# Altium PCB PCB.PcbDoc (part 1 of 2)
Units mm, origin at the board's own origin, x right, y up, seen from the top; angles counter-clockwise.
Board outline 40.89 x 35.18 mm, 4 copper layers (Top Layer, Signal Layer 1, Signal Layer 2, Bottom Layer), stack 1.554 mm thick; 53 components, 28 nets, 142 pads, 33 vias.
Unrouted connection lines stored in the file: 4.
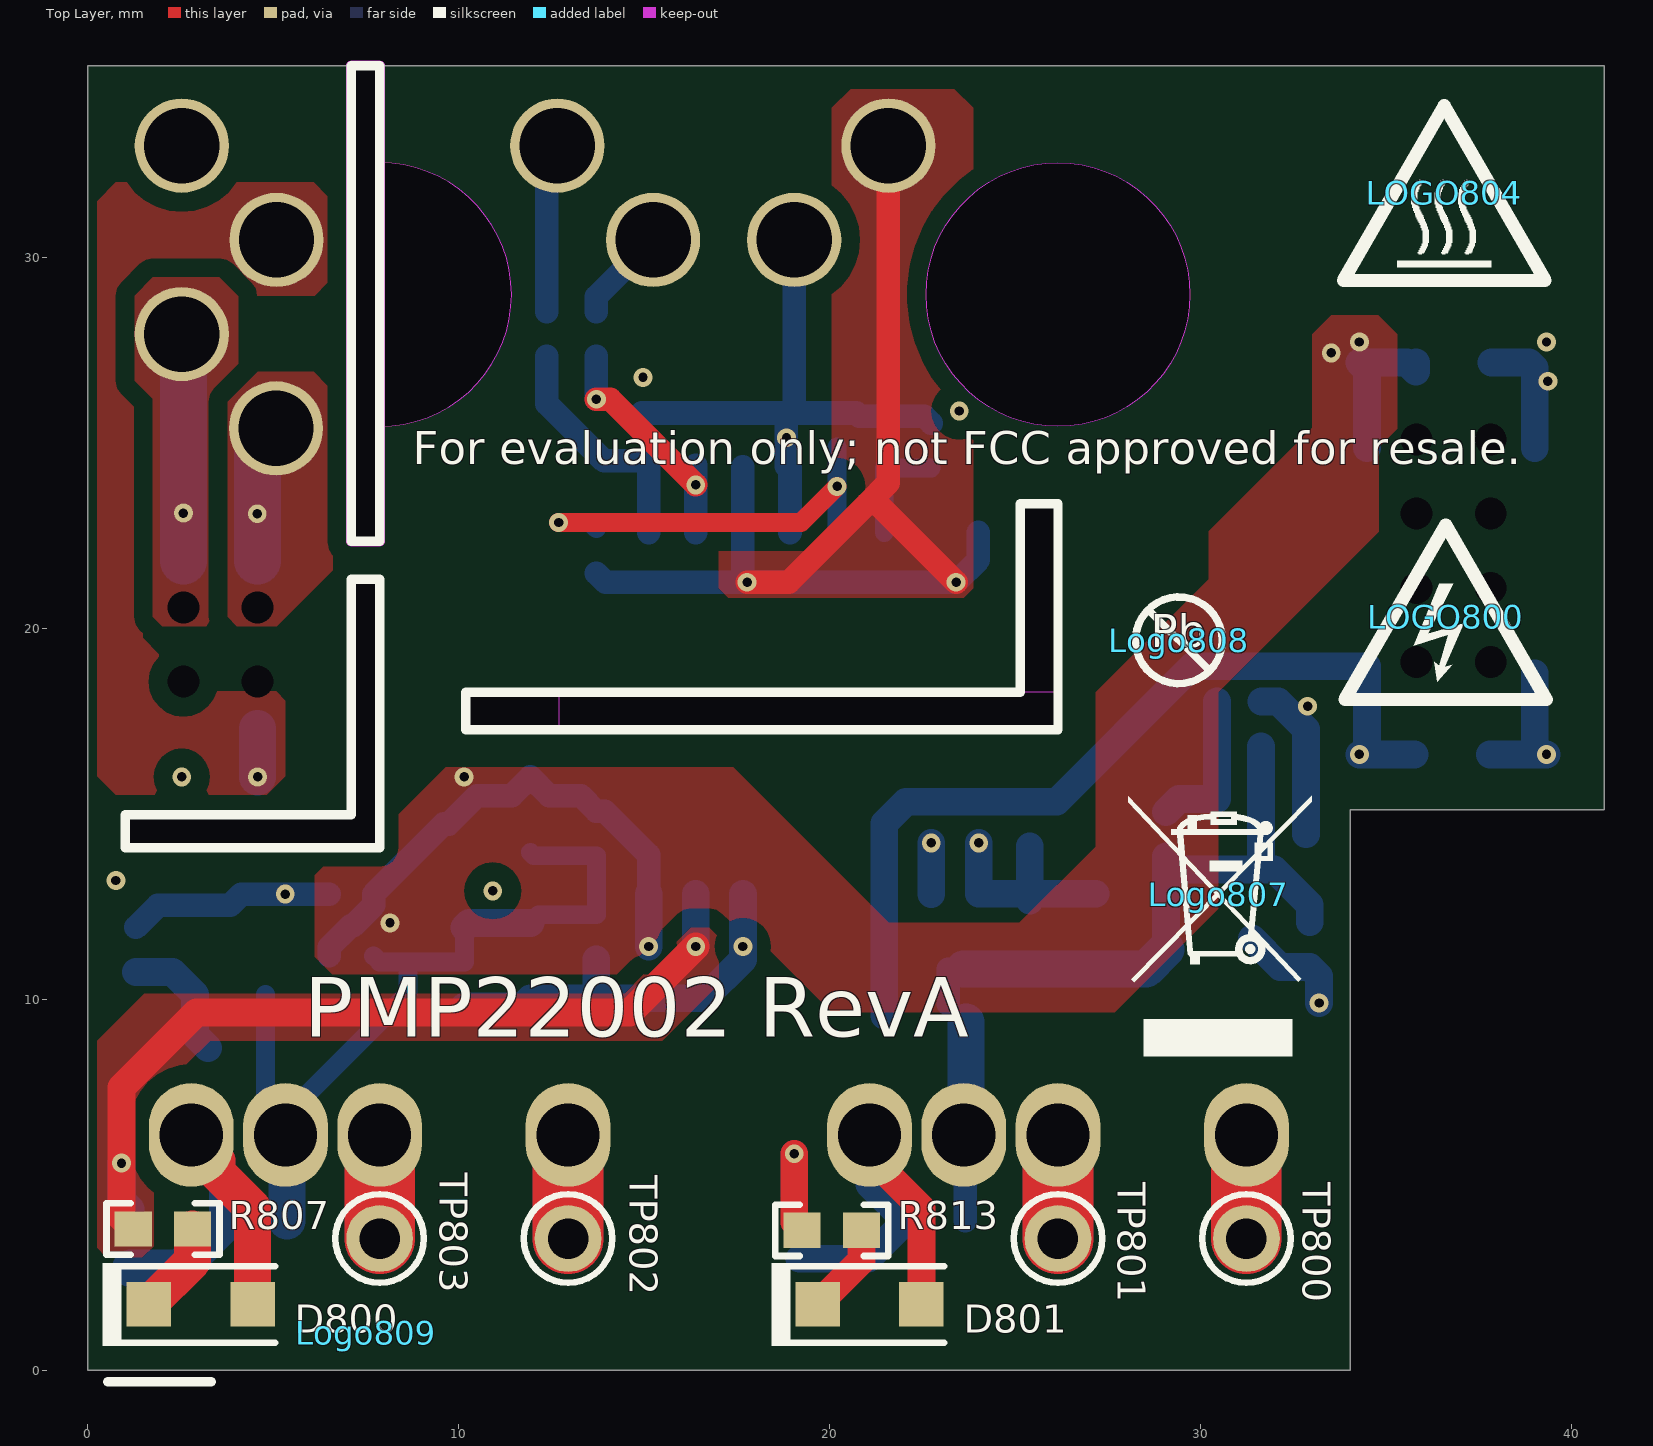
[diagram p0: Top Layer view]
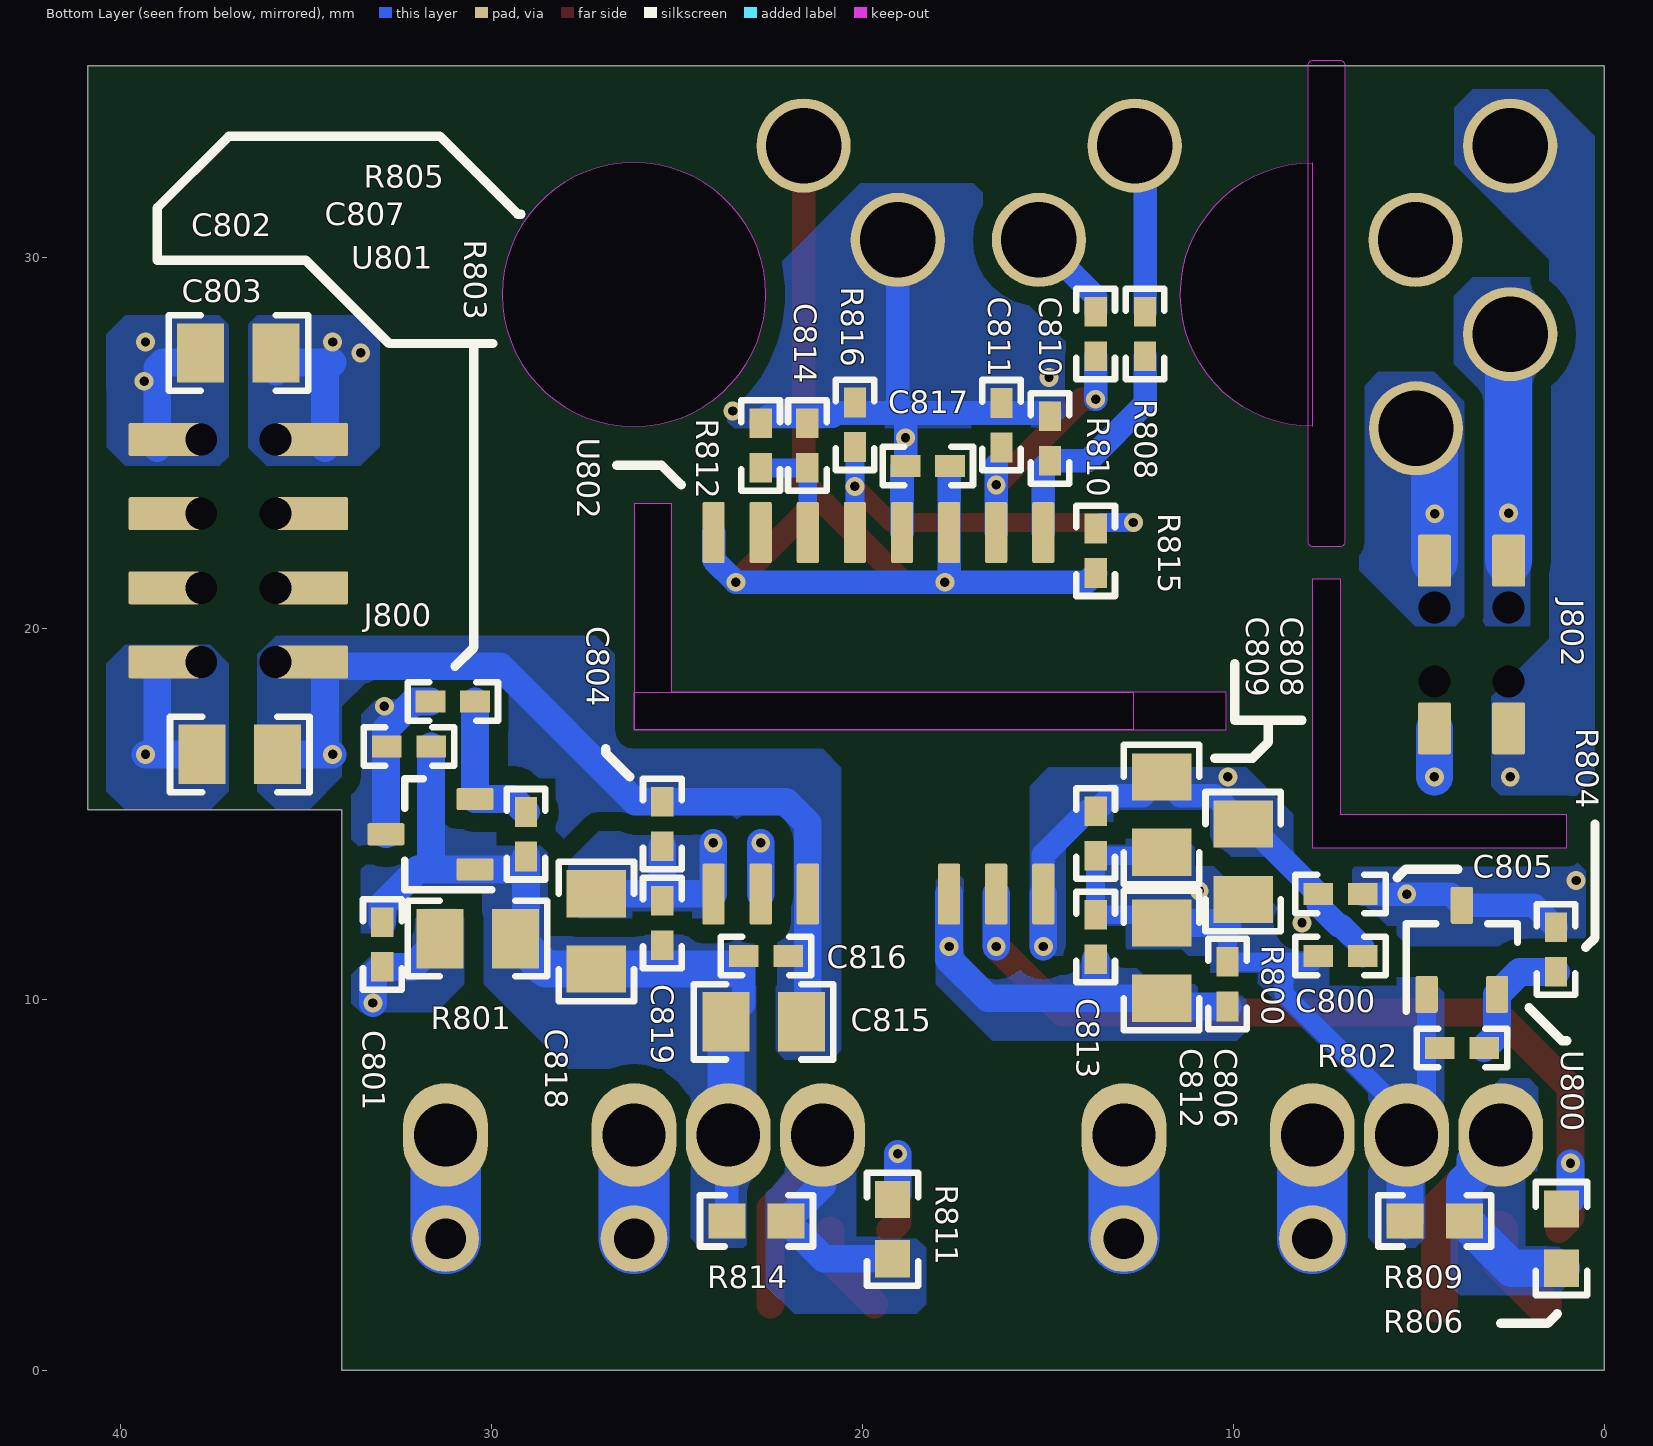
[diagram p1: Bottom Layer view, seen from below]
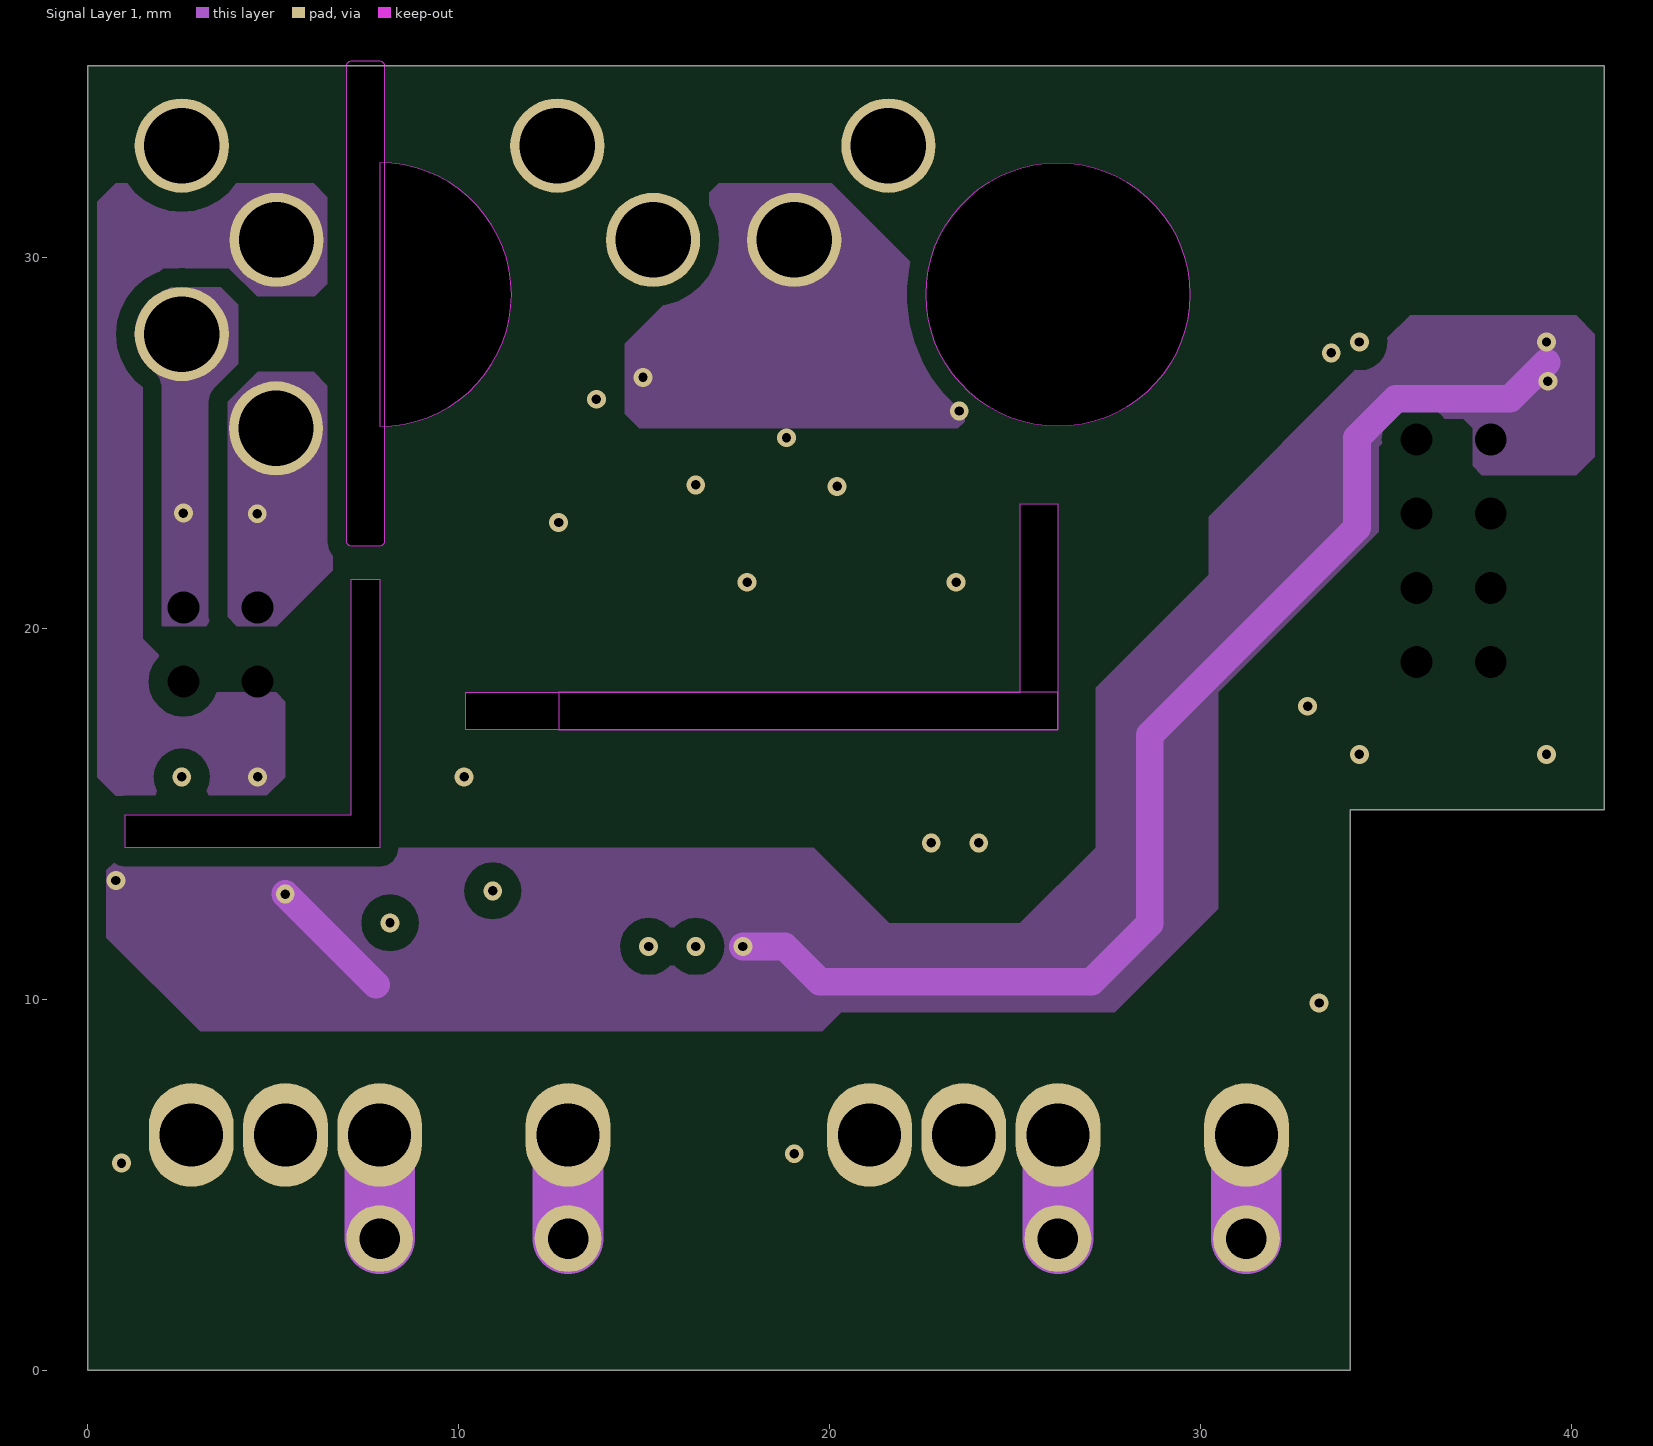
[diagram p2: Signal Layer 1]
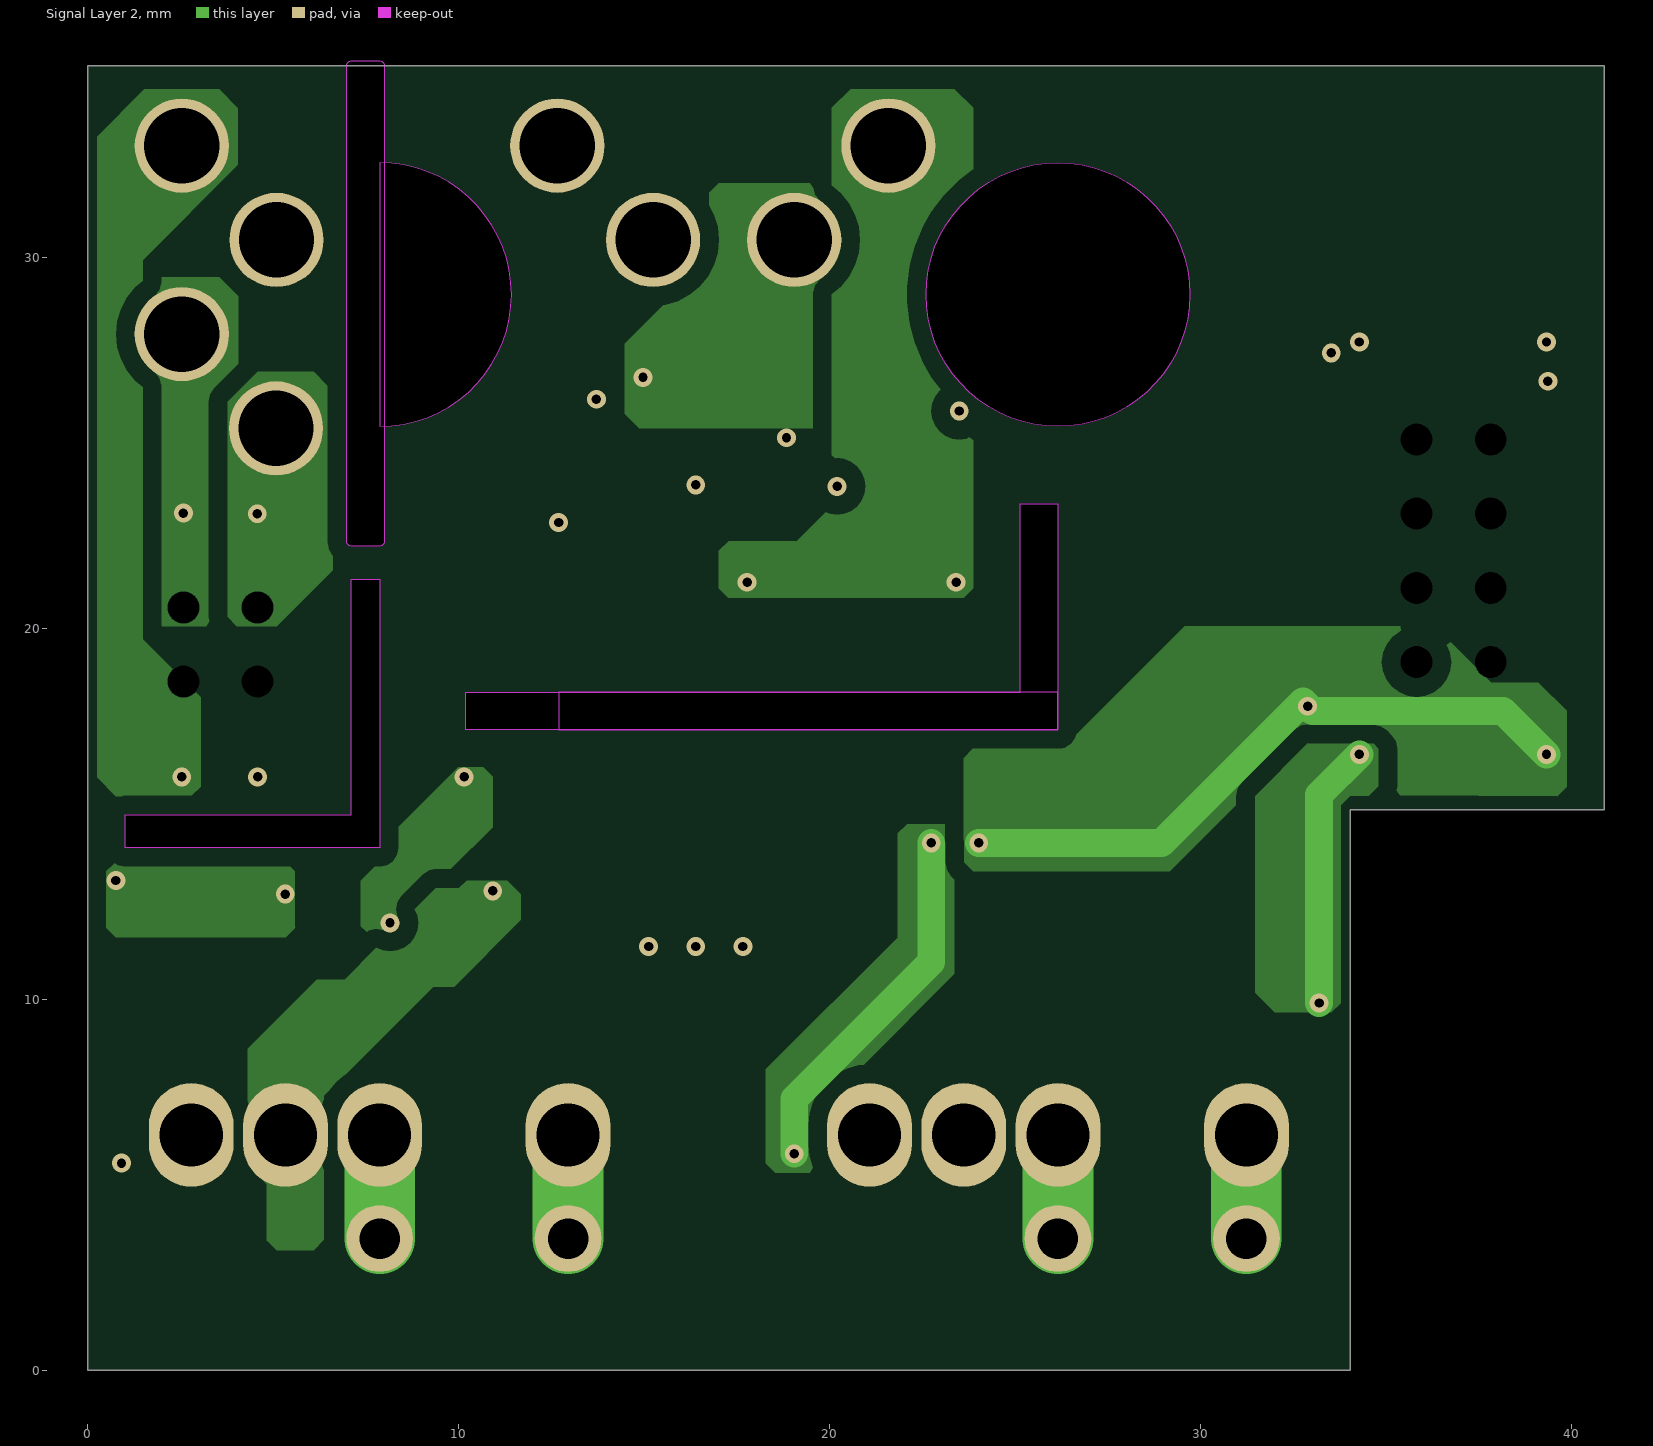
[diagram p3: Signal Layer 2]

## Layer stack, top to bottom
Top Solder: solder mask 0.0102, Solder Resist, Dk 3.5
Top Layer: signal copper 0.0356
Dielectric 3: dielectric 0.1981, Dk 4.2
Signal Layer 1: signal copper 0.0356
Dielectric 2: core 1.016, FR-4, Dk 4.2
Signal Layer 2: signal copper 0.0356
Dielectric 4: dielectric 0.1981, Dk 4.2
Bottom Layer: signal copper 0.0356
Bottom Solder: solder mask 0.0102, Solder Resist, Dk 3.5

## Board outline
0,0 0,35.179 40.894,35.179 40.894,15.113 34.036,15.113 34.036,0
cut-out: 10.191,17.272 10.191,18.288 25.146,18.288 25.146,23.368 26.162,23.368 26.162,17.272
cut-out: 12.7,17.272 26.162,17.272 26.162,18.288 12.7,18.288
cut-out: 1.016,14.097 1.016,14.986 7.112,14.986 7.112,21.336 7.874,21.336 7.874,14.097
cut-out: 7.112,22.225 cw(c7.112,22.352) 6.985,22.352 6.985,35.179 cw(c7.112,35.179) 7.112,35.306 7.874,35.306 cw(c7.874,35.179) 8.001,35.179 8.001,22.352 cw(c7.874,22.352) 7.874,22.225
cut-out: 7.874,25.451 ccw(c7.874,29.007) 7.874,32.563
cut-out: 26.162,25.451 cw(c26.162,29.007) 22.606,29.007 cw(c26.162,29.007) 26.162,32.563 cw(c26.162,29.007) 29.718,29.007 cw(c26.162,29.007)

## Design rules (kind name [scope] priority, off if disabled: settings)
AcuteAngle [All] p1: minimum=4.50000000000000E+0001 checktracksonly=FALSE
AssemblyTestPointUsage [All] p1: valid=2
Clearance Clearance_2 [InNetClass('HV') vs Not InNetClass('HV')] p1: gap=1.27 ignorepadtopadclearanceinfootprint=FALSE except(0: Arc-Hole Track-Hole SMDPad-Hole THPad-Hole Via-Hole Fill-Hole Poly-Hole Region-Hole Text-Hole)
Clearance Clearance_1 [InNetClass('MV') vs Not InNetClass('MV')] p2: gap=0.508 ignorepadtopadclearanceinfootprint=FALSE
Clearance Clearance_Keepouts [((IsTrack Or IsArc) And Not InPoly) And IsFree and IsKeepOut vs ((IsTrack Or IsArc) And Not InPoly) And IsFree and IsKeepOut] p3: gap=0 ignorepadtopadclearanceinfootprint=FALSE
Clearance Clearance_BoardEdge_MountingHoles [OnCopper and InComponentClass('Mounting Holes') vs IsKeepOut] p4: gap=1.016 ignorepadtopadclearanceinfootprint=FALSE except(0: Arc-Hole Track-Hole SMDPad-Hole THPad-Hole Via-Hole Fill-Hole Poly-Hole Region-Hole Text-Hole)
Clearance Clearance_BoardEdge_Poly [OnCopper and InPoly vs IsKeepOut] p5: gap=0.635 ignorepadtopadclearanceinfootprint=FALSE except(0: Arc-Hole Track-Hole SMDPad-Hole THPad-Hole Via-Hole Fill-Hole Poly-Hole Region-Hole Text-Hole)
Clearance Clearance_BoardEdge [OnCopper and Not InComponentClass('Logo') and not InComponentClass('FiducialMark') and not InRegion(1000,500,4000,800) and Not IsKeepout vs IsKeepOut] p6: gap=1.905 ignorepadtopadclearanceinfootprint=FALSE except(0: Arc-Hole Track-Hole SMDPad-Hole THPad-Hole Via-Hole Fill-Hole Poly-Hole Region-Hole Text-Hole)
Clearance Clearance_Poly [InPolygon] p7: gap=0.508 ignorepadtopadclearanceinfootprint=FALSE except(0: Arc-Hole Track-Hole SMDPad-Hole THPad-Hole Via-Hole Fill-Hole Poly-Hole Region-Hole Text-Hole)
Clearance [All] p8: gap=0.2 ignorepadtopadclearanceinfootprint=FALSE except(0: Arc-Hole Track-Hole SMDPad-Hole THPad-Hole Via-Hole Fill-Hole Poly-Hole Region-Hole Text-Hole)
ComponentClearance ComponentClearance_MountingHoles_FiducialMarks [InComponentClass('Mounting Holes') vs InComponentClass('FiducialMark')] p1: gap=0.508 collisioncheckmode=3 verticalgap=0.254 showdistances=FALSE
ComponentClearance ComponentClearance_Shunt [InComponentClass('Header') vs InComponentClass('Shunt')] p2: gap=0 collisioncheckmode=3 verticalgap=0 showdistances=FALSE
ComponentClearance ComponentClearance_Logo [InComponentClass('Logo')] p3: gap=0.127 collisioncheckmode=3 verticalgap=0.254 showdistances=FALSE
ComponentClearance ComponentClearance_ScrewToNut [(HasFootprint('NY PMS 440 0025 PH')) vs (HasFootprint('Keystone_1902C'))] p4: gap=0.508 collisioncheckmode=3 verticalgap=2540 showdistances=FALSE
ComponentClearance ComponentClearance_MountingHoles [InComponentClass('Mounting Holes')] p5: gap=0.508 collisioncheckmode=3 verticalgap=0.254 showdistances=FALSE
ComponentClearance ComponentClearance_SmallPassives [HasFootprint('0201*') or HasFootprint('0402*') or HasFootprint('0508') or HasFootprint('0603*') or HasFootprint('0612') or HasFootprint('0805*') or HasFootprint('0815*') or HasFootprint('0830*') or HasFootprint('1206*') or HasFootprint('1210*') or HasFootprint('1808*') or HasFootprint('1812*') or HasFootprint('1825*') or HasFootprint('2010*') or HasFootprint('2220*') or HasFootprint('2225*') or HasFootprint('2512*') or HasFootprint('2728*') or HasFootprint('3518*') vs HasFootprint('0201*') or HasFootprint('0402*') or HasFootprint('0508') or HasFootprint('0603*') or HasFootprint('0612') or HasFootprint('0805*') or HasFootprint('0815*') or HasFootprint('0830*') or HasFootprint('1206*') or HasFootprint('1210*') or HasFootprint('1808*') or HasFootprint('1812*') or HasFootprint('1825*') or HasFootprint('2010*') or HasFootprint('2220*') or HasFootprint('2225*') or HasFootprint('2512*') or HasFootprint('2728*') or HasFootprint('3518*')] p6: gap=0.508 collisioncheckmode=3 verticalgap=0.508 showdistances=FALSE
ComponentClearance ComponentClearance_THtoSMT [IsThruComponent vs IsSMTComponent] p7: gap=0.254 collisioncheckmode=3 verticalgap=0.254 showdistances=FALSE
ComponentClearance ComponentClearance_THtoTH [IsThruComponent vs IsThruComponent] p8: gap=0.254 collisioncheckmode=3 verticalgap=0.254 showdistances=FALSE
ComponentClearance [All] p9: gap=0.254 collisioncheckmode=3 verticalgap=0.254 showdistances=FALSE
DiffPairsRouting [All] p1: maxlimit=2.54 minlimit=0.254 mostfreqgap=0.254 toplayer_minwidth=0.381 toplayer_maxwidth=0.381 toplayer_prefwidth=0.381 midlayer1_minwidth=0.381 midlayer1_maxwidth=0.381 midlayer1_prefwidth=0.381 midlayer2_minwidth=0.381 midlayer2_maxwidth=0.381 midlayer2_prefwidth=0.381 bottomlayer_minwidth=0.381 bottomlayer_maxwidth=0.381 bottomlayer_prefwidth=0.381 maxuncoupledlength=25.4
FabricationTestPointUsage TestPointUsage [All] p1: valid=2 allowmultiple=FALSE
FabricationTestpoint Testpoint [All] p1: side=3 testpointundercomponent=TRUE minsize=1.016 maxsize=2.54 preferedsize=1.524 minholesize=0 maxholesize=1.016 preferedholesize=0.813 testpointgrid=0.025 allowsidetop=TRUE allowsidebottom=TRUE usegrid=TRUE gridtolerance=0
FanoutControl Fanout_LCC [IsLCC] p1: bgadir=Out bgaviamode=Centered fanoutstyle=Auto fanoutdirection=Alternating viagrid=0.025 // Fanout_LCC (Default Rule)
FanoutControl Fanout_BGA [IsBGA] p2: bgadir=Out bgaviamode=Centered fanoutstyle=Auto fanoutdirection=Alternating viagrid=0.025 // Fanout_BGA (Default Rule)
FanoutControl Fanout_Default [All] p4: bgadir=Out bgaviamode=Centered fanoutstyle=Auto fanoutdirection=Alternating viagrid=0.025 // Fanout_Default (Default Rule)
FanoutControl Fanout_Small [(CompPinCount < 5)] p5: bgadir=Out bgaviamode=Centered fanoutstyle=Auto fanoutdirection=OutThenIn viagrid=0.025 // Fanout_Small (Default Rule)
Height [All] p1: minheight=0 maxheight=76.2 prefheight=12.7
HoleSize [All] p1: absolutevalues=TRUE maxlimit=6.375 minlimit=0.178 maxpercent=80.000 minpercent=20.000
MinimumAnnularRing MinimumAnnularRing_ThermalPadVias [IsVia and InAnyComponent] p1: minimumring=0.15
MinimumAnnularRing [All] p2: minimumring=0.124
MinimumSolderMaskSliver MinimumSolderMaskSliver_Logo [InComponentClass('Logo') vs InComponentClass('Logo')] p1: minsoldermaskwidth=0.018
MinimumSolderMaskSliver [All] p2: minsoldermaskwidth=0.051
PlaneConnect [All] p1: planeconnectstyle=Direct reliefexpansion=0.254 reliefentries=4 reliefconductorwidth=0.254 reliefairgap=0.254
PolygonConnect PolygonConnect_23 [All vs IsNamedPolygon('PGND') Or  IsNamedPolygon('5Vp') Or  IsNamedPolygon('PGND') Or  IsNamedPolygon('PGND') Or  IsNamedPolygon('PGND') Or  IsNamedPolygon('5Vp') Or  IsNamedPolygon('5Vp') Or  IsNamedPolygon('5Vp') Or  IsNamedPolygon('+VA') Or  IsNamedPolygon('-VA') Or  IsNamedPolygon('Vg1') Or  IsNamedPolygon('R806_1') Or  IsNamedPolygon('PGND') Or  IsNamedPolygon('5Vp') Or  IsNamedPolygon('Vg1') Or  IsNamedPolygon('Vg2') Or  IsNamedPolygon('Vg2') Or  IsNamedPolygon('+VB') Or  IsNamedPolygon('R811_1') Or  IsNamedPolygon('+VA') Or  IsNamedPolygon('-VA') Or  IsNamedPolygon('-VB') Or  IsNamedPolygon('-VB') Or  IsNamedPolygon('-VB') Or  IsNamedPolygon('+VB') Or  IsNamedPolygon('+VB') Or  IsNamedPolygon('COMB') Or  IsNamedPolygon('-VB') Or  IsNamedPolygon('VGB') Or  IsNamedPolygon('VGA') Or  IsNamedPolygon('-VA') Or  IsNamedPolygon('+VA') Or  IsNamedPolygon('Coma') Or  IsNamedPolygon('-VA') Or  IsNamedPolygon('+VA') Or  IsNamedPolygon('Coma') Or  IsNamedPolygon('-VA') Or  IsNamedPolygon('PGND') Or  IsNamedPolygon('PGND') Or  IsNamedPolygon('5Vp')] p1: connectstyle=Direct reliefconductorwidth=0.254 reliefentries=4 polygonreliefangle="90 Angle" airgapwidth=0.254
PolygonConnect PolygonConnect_22 [All vs IsNamedPolygon('+VB') Or  IsNamedPolygon('PGND') Or  IsNamedPolygon('VGB') Or  IsNamedPolygon('VGA') Or  IsNamedPolygon('+VA') Or  IsNamedPolygon('-VA') Or  IsNamedPolygon('5Vp') Or  IsNamedPolygon('5Vp') Or  IsNamedPolygon('+VA') Or  IsNamedPolygon('Vg2') Or  IsNamedPolygon('Coma') Or  IsNamedPolygon('-VA') Or  IsNamedPolygon('Vg2') Or  IsNamedPolygon('-VB') Or  IsNamedPolygon('PGND') Or  IsNamedPolygon('Vg2') Or  IsNamedPolygon('PGND') Or  IsNamedPolygon('-VA') Or  IsNamedPolygon('5Vp') Or  IsNamedPolygon('+VA') Or  IsNamedPolygon('5Vp') Or  IsNamedPolygon('PGND') Or  IsNamedPolygon('PGND') Or  IsNamedPolygon('PGND') Or  IsNamedPolygon('Coma') Or  IsNamedPolygon('5Vp') Or  IsNamedPolygon('PGND') Or  IsNamedPolygon('R806_1') Or  IsNamedPolygon('5Vp') Or  IsNamedPolygon('Vg2') Or  IsNamedPolygon('-VA')] p2: connectstyle=Direct reliefconductorwidth=0.254 reliefentries=4 polygonreliefangle="90 Angle" airgapwidth=0.254
PolygonConnect PolygonConnect_21 [All vs IsNamedPolygon('PGND') Or  IsNamedPolygon('VGA') Or  IsNamedPolygon('R806_1') Or  IsNamedPolygon('5Vp') Or  IsNamedPolygon('Vg2') Or  IsNamedPolygon('PGND') Or  IsNamedPolygon('-VA') Or  IsNamedPolygon('Coma') Or  IsNamedPolygon('5Vp') Or  IsNamedPolygon('5Vp') Or  IsNamedPolygon('5Vp') Or  IsNamedPolygon('+VA') Or  IsNamedPolygon('PGND') Or  IsNamedPolygon('5Vp') Or  IsNamedPolygon('Vg2') Or  IsNamedPolygon('-VA') Or  IsNamedPolygon('VGB') Or  IsNamedPolygon('5Vp') Or  IsNamedPolygon('PGND') Or  IsNamedPolygon('+VA') Or  IsNamedPolygon('PGND') Or  IsNamedPolygon('Vg2') Or  IsNamedPolygon('PGND') Or  IsNamedPolygon('+VA') Or  IsNamedPolygon('-VA') Or  IsNamedPolygon('-VA') Or  IsNamedPolygon('Vg2') Or  IsNamedPolygon('Coma') Or  IsNamedPolygon('PGND')] p3: connectstyle=Direct reliefconductorwidth=0.254 reliefentries=4 polygonreliefangle="90 Angle" airgapwidth=0.254
PolygonConnect PolygonConnect_20 [All vs IsNamedPolygon('Vg2') Or  IsNamedPolygon('Vg2') Or  IsNamedPolygon('Vg2') Or  IsNamedPolygon('5Vp') Or  IsNamedPolygon('5Vp') Or  IsNamedPolygon('PGND') Or  IsNamedPolygon('-VA') Or  IsNamedPolygon('-VA') Or  IsNamedPolygon('R806_1') Or  IsNamedPolygon('PGND') Or  IsNamedPolygon('PGND') Or  IsNamedPolygon('Vg2') Or  IsNamedPolygon('Coma') Or  IsNamedPolygon('PGND') Or  IsNamedPolygon('+VA') Or  IsNamedPolygon('+VA') Or  IsNamedPolygon('5Vp') Or  IsNamedPolygon('PGND') Or  IsNamedPolygon('PGND') Or  IsNamedPolygon('5Vp') Or  IsNamedPolygon('PGND') Or  IsNamedPolygon('5Vp') Or  IsNamedPolygon('5Vp')] p4: connectstyle=Direct reliefconductorwidth=0.254 reliefentries=4 polygonreliefangle="90 Angle" airgapwidth=0.254
PolygonConnect PolygonConnect_19 [All vs IsNamedPolygon('PGND') Or  IsNamedPolygon('5Vp') Or  IsNamedPolygon('5Vp') Or  IsNamedPolygon('Vg2') Or  IsNamedPolygon('Vg2') Or  IsNamedPolygon('5Vp') Or  IsNamedPolygon('PGND') Or  IsNamedPolygon('5Vp') Or  IsNamedPolygon('Vg2') Or  IsNamedPolygon('PGND') Or  IsNamedPolygon('PGND') Or  IsNamedPolygon('R806_1') Or  IsNamedPolygon('PGND') Or  IsNamedPolygon('PGND') Or  IsNamedPolygon('Vg2') Or  IsNamedPolygon('5Vp') Or  IsNamedPolygon('-VA') Or  IsNamedPolygon('PGND') Or  IsNamedPolygon('5Vp')] p5: connectstyle=Direct reliefconductorwidth=0.254 reliefentries=4 polygonreliefangle="90 Angle" airgapwidth=0.254
PolygonConnect PolygonConnect_18 [All vs IsNamedPolygon('Vg2') Or  IsNamedPolygon('Vg2') Or  IsNamedPolygon('Vg2')] p6: connectstyle=Direct reliefconductorwidth=0.254 reliefentries=4 polygonreliefangle="90 Angle" airgapwidth=0.254
PolygonConnect PolygonConnect_17 [All vs IsNamedPolygon('4Vb') Or  IsNamedPolygon('4Va') Or  IsNamedPolygon('Comb') Or  IsNamedPolygon('PGND') Or  IsNamedPolygon('5Vp') Or  IsNamedPolygon('Comb') Or  IsNamedPolygon('Coma') Or  IsNamedPolygon('4Vb') Or  IsNamedPolygon('15Vb') Or  IsNamedPolygon('Coma') Or  IsNamedPolygon('15Va') Or  IsNamedPolygon('Comb') Or  IsNamedPolygon('Coma') Or  IsNamedPolygon('Comb') Or  IsNamedPolygon('4Vb') Or  IsNamedPolygon('15Vb') Or  IsNamedPolygon('15Va') Or  IsNamedPolygon('4Vb') Or  IsNamedPolygon('Coma') Or  IsNamedPolygon('4Va') Or  IsNamedPolygon('4Va') Or  IsNamedPolygon('4Va')] p7: connectstyle=Direct reliefconductorwidth=0.254 reliefentries=4 polygonreliefangle="90 Angle" airgapwidth=0.254
PolygonConnect PolygonConnect_16 [All vs IsNamedPolygon('15Va') Or  IsNamedPolygon('Coma') Or  IsNamedPolygon('4Vb') Or  IsNamedPolygon('Comb') Or  IsNamedPolygon('PGND') Or  IsNamedPolygon('15Vb') Or  IsNamedPolygon('4Va') Or  IsNamedPolygon('5Vp')] p8: connectstyle=Direct reliefconductorwidth=0.254 reliefentries=4 polygonreliefangle="90 Angle" airgapwidth=0.254
PolygonConnect PolygonConnect_15 [All vs IsNamedPolygon('C109_2') Or  IsNamedPolygon('C107_2') Or  IsNamedPolygon('HV') Or  IsNamedPolygon('Q203_5') Or  IsNamedPolygon('C107_2') Or  IsNamedPolygon('HS') Or  IsNamedPolygon('Q201_5') Or  IsNamedPolygon('Q203_5') Or  IsNamedPolygon('C106_2') Or  IsNamedPolygon('C108_2') Or  IsNamedPolygon('Vout') Or  IsNamedPolygon('Q203_5') Or  IsNamedPolygon('C108_2') Or  IsNamedPolygon('C113_2') Or  IsNamedPolygon('Q203_5') Or  IsNamedPolygon('Q201_5') Or  IsNamedPolygon('C107_2') Or  IsNamedPolygon('C102_1') Or  IsNamedPolygon('SGND') Or  IsNamedPolygon('GND') Or  IsNamedPolygon('SGND') Or  IsNamedPolygon('GND') Or  IsNamedPolygon('IN+') Or  IsNamedPolygon('IN+') Or  IsNamedPolygon('Q201_5') Or  IsNamedPolygon('Q201_5') Or  IsNamedPolygon('SGND') Or  IsNamedPolygon('SGND') Or  IsNamedPolygon('Vout') Or  IsNamedPolygon('Vout') Or  IsNamedPolygon('IN+') Or  IsNamedPolygon('GND') Or  IsNamedPolygon('IN+') Or  IsNamedPolygon('GND')] p9: connectstyle=Direct reliefconductorwidth=0.254 reliefentries=4 polygonreliefangle="90 Angle" airgapwidth=0.254
PolygonConnect PolygonConnect_14 [All vs IsNamedPolygon('C106_2') Or  IsNamedPolygon('C107_2') Or  IsNamedPolygon('C107_2') Or  IsNamedPolygon('C107_2') Or  IsNamedPolygon('C102_1') Or  IsNamedPolygon('Q203_5') Or  IsNamedPolygon('Vout') Or  IsNamedPolygon('Q203_5') Or  IsNamedPolygon('Q203_5') Or  IsNamedPolygon('Q201_5') Or  IsNamedPolygon('C108_2') Or  IsNamedPolygon('Q203_5') Or  IsNamedPolygon('HS') Or  IsNamedPolygon('HV') Or  IsNamedPolygon('C108_2') Or  IsNamedPolygon('Q201_5') Or  IsNamedPolygon('C109_2') Or  IsNamedPolygon('Q201_5') Or  IsNamedPolygon('Q201_5') Or  IsNamedPolygon('C113_2')] p10: connectstyle=Direct reliefconductorwidth=0.254 reliefentries=4 polygonreliefangle="90 Angle" airgapwidth=0.254
PolygonConnect PolygonConnect_13 [All vs IsNamedPolygon('C102_1') Or  IsNamedPolygon('HV') Or  IsNamedPolygon('C107_2') Or  IsNamedPolygon('C109_2') Or  IsNamedPolygon('C107_2') Or  IsNamedPolygon('C108_2') Or  IsNamedPolygon('C106_2') Or  IsNamedPolygon('C108_2') Or  IsNamedPolygon('C113_2') Or  IsNamedPolygon('C107_2')] p11: connectstyle=Direct reliefconductorwidth=0.254 reliefentries=4 polygonreliefangle="90 Angle" airgapwidth=0.254
PolygonConnect PolygonConnect_12 [All vs IsNamedPolygon('C107_2') Or  IsNamedPolygon('C113_2') Or  IsNamedPolygon('C106_2') Or  IsNamedPolygon('C107_2') Or  IsNamedPolygon('C107_2') Or  IsNamedPolygon('C102_1')] p12: connectstyle=Direct reliefconductorwidth=0.254 reliefentries=4 polygonreliefangle="90 Angle" airgapwidth=0.254
PolygonConnect PolygonConnect_11 [All vs IsNamedPolygon('C106_2') Or  IsNamedPolygon('C102_1') Or  IsNamedPolygon('C107_2') Or  IsNamedPolygon('C107_2') Or  IsNamedPolygon('C107_2')] p13: connectstyle=Direct reliefconductorwidth=0.254 reliefentries=4 polygonreliefangle="90 Angle" airgapwidth=0.254
PolygonConnect PolygonConnect_10 [All vs IsNamedPolygon('C106_2')] p14: connectstyle=Direct reliefconductorwidth=0.254 reliefentries=4 polygonreliefangle="90 Angle" airgapwidth=0.254
PolygonConnect PolygonConnect_9 [All vs IsNamedPolygon('C11_1') Or  IsNamedPolygon('Vin') Or  IsNamedPolygon('Vin') Or  IsNamedPolygon('5V') Or  IsNamedPolygon('D6_2') Or  IsNamedPolygon('Q3_3') Or  IsNamedPolygon('GND2') Or  IsNamedPolygon('GND2') Or  IsNamedPolygon('GND') Or  IsNamedPolygon('Q3_4') Or  IsNamedPolygon('12V5') Or  IsNamedPolygon('GND') Or  IsNamedPolygon('12V5') Or  IsNamedPolygon('D3_1')] p15: connectstyle=Direct reliefconductorwidth=0.254 reliefentries=4 polygonreliefangle="90 Angle" airgapwidth=0.254
PolygonConnect PolygonConnect_8 [All vs IsNamedPolygon('C11_1') Or  IsNamedPolygon('Vin') Or  IsNamedPolygon('12V5') Or  IsNamedPolygon('Q3_3') Or  IsNamedPolygon('GND2') Or  IsNamedPolygon('GND2') Or  IsNamedPolygon('5V') Or  IsNamedPolygon('Q3_4') Or  IsNamedPolygon('12V5')] p16: connectstyle=Direct reliefconductorwidth=0.254 reliefentries=4 polygonreliefangle="90 Angle" airgapwidth=0.254
PolygonConnect PolygonConnect_7 [All vs IsNamedPolygon('GND2') Or  IsNamedPolygon('GND2') Or  IsNamedPolygon('5V') Or  IsNamedPolygon('12V5') Or  IsNamedPolygon('12V5') Or  IsNamedPolygon('C11_1')] p17: connectstyle=Direct reliefconductorwidth=0.254 reliefentries=4 polygonreliefangle="90 Angle" airgapwidth=0.254
PolygonConnect PolygonConnect_6 [All vs IsNamedPolygon('GND2') Or  IsNamedPolygon('SGND') Or  IsNamedPolygon('GND1') Or  IsNamedPolygon('C901_1') Or  IsNamedPolygon('SGND') Or  IsNamedPolygon('GND2') Or  IsNamedPolygon('GND1')] p18: connectstyle=Direct reliefconductorwidth=0.254 reliefentries=4 polygonreliefangle="90 Angle" airgapwidth=0.254
PolygonConnect PolygonConnect_5 [All vs IsNamedPolygon('GND1') Or  IsNamedPolygon('GND1')] p19: connectstyle=Direct reliefconductorwidth=0.254 reliefentries=4 polygonreliefangle="90 Angle" airgapwidth=0.254
PolygonConnect PolygonConnect_4 [All vs IsNamedPolygon('C21_1') Or  IsNamedPolygon('C5_1') Or  IsNamedPolygon('C12_2') Or  IsNamedPolygon('C2_2') Or  IsNamedPolygon('C13_1') Or  IsNamedPolygon('C28_1') Or  IsNamedPolygon('C6_1') Or  IsNamedPolygon('GND') Or  IsNamedPolygon('GND2') Or  IsNamedPolygon('C14_1') Or  IsNamedPolygon('C13_1') Or  IsNamedPolygon('Q1_3') Or  IsNamedPolygon('C14_1') Or  IsNamedPolygon('C5_1') Or  IsNamedPolygon('GND2') Or  IsNamedPolygon('C28_1') Or  IsNamedPolygon('D5_2') Or  IsNamedPolygon('D6_2') Or  IsNamedPolygon('D2_1') Or  IsNamedPolygon('C12_2') Or  IsNamedPolygon('D2_1') Or  IsNamedPolygon('C4_1') Or  IsNamedPolygon('C4_1') Or  IsNamedPolygon('C2_2') Or  IsNamedPolygon('GND') Or  IsNamedPolygon('C33_1') Or  IsNamedPolygon('C9_1')] p20: connectstyle=Direct reliefconductorwidth=0.254 reliefentries=4 polygonreliefangle="90 Angle" airgapwidth=0.254
PolygonConnect PolygonConnect_3 [All vs IsNamedPolygon('C28_1') Or  IsNamedPolygon('C12_2') Or  IsNamedPolygon('C28_1') Or  IsNamedPolygon('C9_1') Or  IsNamedPolygon('D5_2') Or  IsNamedPolygon('C12_2') Or  IsNamedPolygon('C2_2') Or  IsNamedPolygon('C14_1') Or  IsNamedPolygon('C4_1') Or  IsNamedPolygon('C14_1') Or  IsNamedPolygon('D6_2') Or  IsNamedPolygon('GND2') Or  IsNamedPolygon('Q1_3') Or  IsNamedPolygon('C5_1') Or  IsNamedPolygon('D2_1') Or  IsNamedPolygon('C4_1') Or  IsNamedPolygon('C13_1') Or  IsNamedPolygon('C5_1') Or  IsNamedPolygon('C13_1') Or  IsNamedPolygon('C33_1') Or  IsNamedPolygon('D2_1') Or  IsNamedPolygon('GND') Or  IsNamedPolygon('GND') Or  IsNamedPolygon('GND2') Or  IsNamedPolygon('C2_2') Or  IsNamedPolygon('C6_1') Or  IsNamedPolygon('C21_1')] p21: connectstyle=Direct reliefconductorwidth=0.254 reliefentries=4 polygonreliefangle="90 Angle" airgapwidth=0.254
PolygonConnect PolygonConnect_2 [All vs IsNamedPolygon('C21_1') Or  IsNamedPolygon('C4_1') Or  IsNamedPolygon('D5_2') Or  IsNamedPolygon('C5_1') Or  IsNamedPolygon('C14_1') Or  IsNamedPolygon('C13_1') Or  IsNamedPolygon('C4_1') Or  IsNamedPolygon('C33_1') Or  IsNamedPolygon('C12_2') Or  IsNamedPolygon('D2_1') Or  IsNamedPolygon('C2_2') Or  IsNamedPolygon('C28_1') Or  IsNamedPolygon('C12_2') Or  IsNamedPolygon('D2_1') Or  IsNamedPolygon('C5_1') Or  IsNamedPolygon('Q1_3') Or  IsNamedPolygon('GND') Or  IsNamedPolygon('D6_2') Or  IsNamedPolygon('C6_1') Or  IsNamedPolygon('C2_2') Or  IsNamedPolygon('C14_1') Or  IsNamedPolygon('C28_1') Or  IsNamedPolygon('C13_1') Or  IsNamedPolygon('C9_1') Or  IsNamedPolygon('GND')] p22: connectstyle=Direct reliefconductorwidth=0.254 reliefentries=4 polygonreliefangle="90 Angle" airgapwidth=0.254
PolygonConnect PolygonConnect_1 [All vs IsNamedPolygon('C28_1') Or  IsNamedPolygon('D5_2') Or  IsNamedPolygon('C5_1') Or  IsNamedPolygon('C5_1') Or  IsNamedPolygon('D2_1') Or  IsNamedPolygon('C21_1') Or  IsNamedPolygon('C9_1') Or  IsNamedPolygon('C4_1') Or  IsNamedPolygon('C14_1') Or  IsNamedPolygon('C28_1') Or  IsNamedPolygon('C6_1') Or  IsNamedPolygon('C12_2') Or  IsNamedPolygon('C33_1') Or  IsNamedPolygon('C4_1') Or  IsNamedPolygon('C13_1') Or  IsNamedPolygon('C12_2') Or  IsNamedPolygon('D6_2') Or  IsNamedPolygon('C2_2') Or  IsNamedPolygon('C14_1') Or  IsNamedPolygon('D2_1') Or  IsNamedPolygon('C2_2') Or  IsNamedPolygon('C13_1')] p23: connectstyle=Direct reliefconductorwidth=0.254 reliefentries=4 polygonreliefangle="90 Angle" airgapwidth=0.254
PolygonConnect [All] p24: connectstyle=Relief reliefconductorwidth=0.254 reliefentries=4 polygonreliefangle="90 Angle" airgapwidth=0.254
RoutingVias ThermalPadVias [IsVia and InAnyComponent] p1: holewidth=0.2 width=0.5 viastyle="Through Hole" minholewidth=0.2 minwidth=0.5 maxholewidth=0.33 maxwidth=0.6
RoutingVias [All] p2: holewidth=0.406 width=0.864 viastyle="Through Hole" minholewidth=0.2 minwidth=0.508 maxholewidth=1.016 maxwidth=1.651
SilkToBoardRegionClearance [Not ((IsComment or IsDesignator) And (Hide <> 'False')) and not InRegion(1000,500,4000,800)] p1:
SilkToSilkClearance SilkToSilkClearance_Pb-FreeLogo [(HasFootprint('Pb-Free_Overlay_Medium') OR HasFootprint('Pb-Free_Overlay_Small')) vs (HasFootprint('Pb-Free_Overlay_Medium') OR HasFootprint('Pb-Free_Overlay_Small'))] p1: silktosilkclearance=0
SilkToSilkClearance [All] p2: silktosilkclearance=0.025
SilkToSolderMaskClearance "Silk to Solder Mask Opening" [All] p1: minsilkscreentomaskgap=0.025 clearancetoexposedcopper=FALSE
SolderMaskExpansion [All] p1: expansion=0.05
Width [All] p1: maxlimit=2.54 minlimit=0.152 preferedwidth=0.254 checkconnectedcopper=TRUE
14 further rules are at their usual default settings.

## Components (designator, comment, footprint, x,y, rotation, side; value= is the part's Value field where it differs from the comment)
C800 "C1005X7R1H104K050BB" 0402 7.112,11.176 r0 bottom value=0.1uF
C801 "C1005X7R1H104K050BB" 0402 32.949,11.481 r90 bottom value=0.1uF
C802 "CGA4J3X5R1H475K125AB" 0805_HV 36.792,16.608 r0 bottom value=4.7uF
C803 "CGA4J3X5R1H475K125AB" 0805_HV 36.83,27.432 r0 bottom value=4.7uF
C804 "C1005X7R1H104K050BB" 0402 25.4,14.732 r270 bottom value=0.1uF
C805 "C1005X7R1H104K050BB" 0402 7.112,12.842 r180 bottom value=0.1uF
C806 "C1005X7R1H104K050BB" 0402 10.16,10.414 r270 bottom value=0.1uF
C807 "C1005X7R1H104K050BB" 0402 32.233,16.821 r0 bottom value=0.1uF
C808 "CGA4J3X5R1H475K125AB" 0805_HV 11.938,14.986 r270 bottom value=4.7uF
C809 "GRM155R71H103KA88D" 0402 13.716,14.478 r270 bottom value=0.01uF
C810 "0402YC101KAT2A" 0402 14.947,25.122 r90 bottom value=100pF
C811 "0402YC101KAT2A" 0402 16.256,25.484 r90 bottom value=100pF
C812 "CGA4J3X5R1H475K125AB" 0805_HV 11.938,11.049 r270 bottom value=4.7uF
C813 "GRM155R71H103KA88D" 0402 13.716,11.684 r270 bottom value=0.01uF
C814 "885012205027" 0402 21.489,24.934 r90 bottom value=2200pF
C815 "CGA4J3X5R1H475K125AB" 0805_HV 22.667,9.398 r0 bottom value=4.7uF
C816 "GRM155R71H103KA88D" 0402 22.606,11.176 r0 bottom value=0.01uF
C817 "0402YC104KAT2A" 0402 18.242,24.384 r0 bottom value=0.1uF
C818 "CGA4J3X5R1H475K125AB" 0805_HV 27.178,11.836 r90 bottom value=4.7uF
C819 "GRM155R71H103KA88D" 0402 25.4,12.065 r90 bottom value=0.01uF
D800 "SS14FL" SOD-123F 3.048,1.778 r0 top value=40V
D801 "SS14FL" SOD-123F 21.082,1.778 r0 top value=40V
J800 "CLT-104-02-G-D" FP-CLT-104-02-G-D_HDR8-MFG 36.83,22.098 r90 bottom locked
J802 "CLT-102-02-G-D-BE" Samtec_CLT-102-02-x-D-BE 3.582,19.571 r180 bottom
LOGO800 "DANGER HIGH VOLTAGE" IEC_HighVoltage_Small 36.614,20.32 r0 top
LOGO804 "CAUTION HOT SURFACE" IEC_HotSurface_Small 36.576,31.75 r0 top
Logo807 "WEEE logo" WEEE_Minimum 30.48,12.842 r0 top
Logo808 "Pb-Free Symbol" Pb-Free_Overlay_Small 29.421,19.685 r0 top
Logo809 "FCC disclaimer" FCC_disclaimer 7.493,1.016 r90 top
R800 "AC0805JR-074K7L" 0805_HV 9.738,13.716 r90 bottom value=4.7k
R801 "AC0805JR-074K7L" 0805_HV 30.378,11.643 r0 bottom value=4.7k
R802 "CRCW04023K01FKED" 0402 3.843,8.691 r0 bottom value=3.01k
R803 "CRCW04023K01FKED" 0402 29.075,14.455 r270 bottom value=3.01k
R804 "CRCW04024K99FKED" 0402 1.303,11.345 r270 bottom value=4.99k
R805 "CRCW04024K99FKED" 0402 31.048,18.034 r180 bottom value=4.99k
R806 "CRCW06035R11FKEA" 0603 1.157,3.556 r270 bottom value=5.11
R807 "RC0603FR-071RL" 0603 2.032,3.81 r0 top value=1.00
R808 "CRCW04020000Z0ED" 0402 12.383,27.94 r270 bottom value=0
R809 "CRCW060310K0FKEA" 0603 4.572,4.031 r180 bottom value=10.0k
R810 "CRCW04020000Z0ED" 0402 13.716,27.94 r270 bottom value=0
R811 "CRCW06035R11FKEA" 0603 19.191,3.81 r270 bottom value=5.11
R812 "CRCW04023K09FKED" 0402 22.747,24.934 r270 bottom value=3.09k
R813 "RC0603FR-071RL" 0603 20.066,3.777 r0 top value=1.00
R814 "CRCW060310K0FKEA" 0603 22.86,4.031 r180 bottom value=10.0k
R815 "CRCW04025K10JNED" 0402 13.716,22.098 r270 bottom value=5.1k
R816 "CRCW04025K10JNED" 0402 20.207,25.495 r270 bottom value=5.1k
TP800 "3104-2-00-34-00-00-08-0" 3104-2 31.242,3.556 r90 top locked
TP801 "3104-2-00-34-00-00-08-0" 3104-2 26.162,3.556 r90 top locked
TP802 "3104-2-00-34-00-00-08-0" 3104-2 12.954,3.556 r90 top locked
TP803 "3104-2-00-34-00-00-08-0" 3104-2 7.874,3.556 r90 top locked
U800 "TL431AQDBZRQ1" DBZ0003A_N 3.843,11.337 r90 bottom
U801 "TL431AQDBZRQ1" DBZ0003A_N 31.648,14.455 r0 bottom
U802 "UCC21530QDWKRQ1" DWK0014A 19.572,17.716 r270 bottom

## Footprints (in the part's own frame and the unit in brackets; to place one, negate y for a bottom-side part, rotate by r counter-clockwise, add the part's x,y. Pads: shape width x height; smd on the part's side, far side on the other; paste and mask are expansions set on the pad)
0402 [mm] "0402 from SM-752 data"
  rect 0.8x0.6 smd: 1(-0.6,0) 2(0.6,0)
  silkscreen extent -1.22,-0.52 1.22,0.52, body extent -0.55,-0.3 0.55,0.3, height 0.6
0603 [mm] "0603 from SM-752 data"
  rect 1x0.95 smd: 1(-0.8,0) 2(0.8,0)
  silkscreen extent -1.52,-0.69 1.52,0.69, body extent -0.87,-0.47 0.87,0.47, height 1
0805_HV [mil] "0805 with 30mil clearance between pads"
  rect 50x63 smd: 1(-40,0) 2(40,0)
  silkscreen extent -74,-40 74,40, body extent -43,-29 43,29, height 57
3104-2 [mm] "Mill-Max Printed Circuit Pins"
  round 1.8 hole 1.092: 1(0,0)
  silkscreen extent -1.19,-1.19 1.19,1.19, body extent -0.88,-0.89 0.9,0.89, height 1.68
DBZ0003A_N [mm] "SOT23, 3-Leads, Body 2.9x1.3mm, Pitch 0.95mm, Lead Span 2.4mm, IPC Medium Density"
  rrect17% 1x0.6 smd: 1(-1.2,0.95) 2(-1.2,-0.95) 3(1.2,0)
  silkscreen extent -1.65,-1.5 0.7,1.5, body extent -1.26,-1.46 1.26,1.46, height 0.98
DWK0014A [mm] "SOIC-14"
  rrect17% 1.65x0.6 smd: 1(-4.875,4.445) 2(-4.875,3.175) 3(-4.875,1.905) 4(-4.875,0.635) 5(-4.875,-0.635) 6(-4.875,-1.905) 7(-4.875,-3.175) 8(-4.875,-4.445) 9(4.875,-4.445) 10(4.875,-3.175) 11(4.875,-1.905) 14(4.875,1.905) 15(4.875,3.175) 16(4.875,4.445)
  body extent -5.17,-5.15 5.17,5.15, height 2.59
FCC_disclaimer [mm]
FP-CLT-104-02-G-D_HDR8-MFG [mm]
  rrect11% 0.89x1.91 smd paste+0 mask+0: 1(3,-2.005) 2(3,2.005) 3(1,-2.005) 4(1,2.005) 5(-1,-2.005) 6(-1,2.005) 7(-3,-2.005) 8(-3,2.005)
  body extent -4,-2.58 4,2.58, height 2.32
IEC_HighVoltage_Small [mm]
  silkscreen extent -2.72,-2.24 2.72,2.47
IEC_HotSurface_Small [mm]
  silkscreen extent -2.72,-2.36 2.72,2.35
Pb-Free_Overlay_Small [mm]
  silkscreen extent -1.16,-1.17 1.17,1.17
Samtec_CLT-102-02-x-D-BE [mm] "Receptacle, 2mm, 2x2, SMT"
  rrect11% 0.89x1.4 smd: 1(-1,2.26) 2(-1,-2.26) 3(1,2.26) 4(1,-2.26)
  round 0.56 hole 0.86 unplated mask+0.102: ""(-1,-1) ""(-1,1) ""(1,-1) ""(1,1)
  body extent -2,-2.58 2,2.58, height 2.29
SOD-123F [mm] "NXP recommended land pattern"
  rect 1.2x1.2 smd paste-0.05: 1(-1.4,0) 2(1.4,0)
  silkscreen extent -2.64,-1.12 2.01,1.12, body extent -1.8,-0.85 1.8,0.85, height 1.2
WEEE_Minimum [mm] "WEEElie bin"
  silkscreen extent -2.42,-4.38 2.52,2.65

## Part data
C800 C801 C804 C805 C806 C807: "CAP, CERM, 0.1 µF, 50 V,+/- 10%, X7R, 0402", Cap_Case=0402, Manufacturer=TDK, Supplier Part Number 1=445-5932-1-ND, TempCo=X7R, Tolerance_%=10, Value1="0.039064 ohm", Value2=50V, ValueDisplayed=0.1µF
C802 C803 C808 C812 C815 C818: library part GRT21BR61H475KE13L, "CAP, CERM, 4.7 µF, 50 V,+/- 10%, X5R, AEC-Q200 Grade 3, 0805", Cap_Case=0805, Manufacturer=TDK, TempCo=X5R, Tolerance_%=10, Value2=50V, ValueDisplayed=4.7µF
C809 C813 C816 C819: "CAP, CERM, 0.01 µF, 50 V,+/- 10%, X7R, 0402", Cap_Case=0402, Manufacturer=MuRata, Supplier Part Number 1=490-4516-1-ND, TempCo=X7R, Tolerance_%=10, Value2=50V, ValueDisplayed=0.01µF
C810 C811: "CAP, CERM, 100 pF, 16 V,+/- 10%, X7R, 0402", Cap_Case=0402, Manufacturer=AVX, Supplier Part Number 1=478-7887-1-ND, TempCo=X7R, Tolerance_%=10, Value2=16V, ValueDisplayed=100pF
C814: "CAP, CERM, 2200 pF, 16 V,+/- 10%, X7R, 0402", Cap_Case=0402, Manufacturer="Wurth Elektronik", TempCo=X7R, Tolerance_%=10, Value2=16V, ValueDisplayed=2200pF
C817: "CAP, CERM, 0.1 µF, 16 V,+/- 10%, X7R, 0402", Cap_Case=0402, Manufacturer=AVX, Supplier Part Number 1=478-7888-1-ND, TempCo=X7R, Tolerance_%=10, Value2=16V, ValueDisplayed=0.1µF
D800 D801: library part CMP-0028801-2, "Diode, Schottky, 40 V, 1 A, AEC-Q101, SOD-123F", Manufacturer="Fairchild Semiconductor", Value1=1A, Value2=0.55V
J800: library part CMP-0086478-1, "CONN RCPT 8POS 0.079 GOLD SMD", Current_A=4.1A, Manufacturer=Samtec
J802: library part CMP-0082275-1, "Receptacle, 2mm, 2x2, Gold, SMT", Color=Black, Current_A=4.1A, Manufacturer=Samtec, Supplier Part Number 1=SAM11007-ND
LOGO800: library part IEC_HighVoltage, "IEC 61010-1 High Voltage Warning"
LOGO804: library part IEC_HotSurface, "IEC 61010-1 Hot Surface Warning"
Logo807: library part CMP-0074769-1
Logo808: library part CMP-0074839-1
Logo809: library part CMP-0074847-1, "FCC_disclaimer"
R800 R801: library part CRCW08054K70JNEA, "RES, 4.7 k, 5%, 0.125 W, 0805", Manufacturer="Yageo America", Power_W=0.125, TempCo="200 ppm/C", Tolerance_%=5, Value1=5%, Value2=0.125W, Value_Code=4k70, ValueDisplayed=4.7k
R802 R803: "RES, 3.01 k, 1%, 0.063 W, 0402", Manufacturer=Vishay-Dale, Power_W=0.063, Supplier Part Number 1=541-3.01KLCT-ND, TempCo="100 ppm/C", Tolerance_%=1, Value1=1%, Value2=0.063W, Value_Code=3k01, ValueDisplayed=3.01k
R804 R805: "RES, 4.99 k, 1%, 0.063 W, 0402", Manufacturer=Vishay-Dale, Power_W=0.063, Supplier Part Number 1=541-4.99KLCT-ND, TempCo="100 ppm/C", Tolerance_%=1, Value1=1%, Value2=0.063W, Value_Code=4k99, ValueDisplayed=4.99k
R806 R811: "RES, 5.11, 1%, 0.1 W, 0603", Manufacturer=Vishay-Dale, Power_W=0.1, Supplier Part Number 1=541-5.11HHCT-ND, TempCo="100 ppm/C", Tolerance_%=1, Value1=1%, Value2=0.1W, Value_Code=5R11, ValueDisplayed=5.11
R807 R813: "RES, 1.00, 1%, 0.1 W, 0603", Manufacturer="Yageo America", Power_W=0.1, Supplier Part Number 1=311-1.00HRCT-ND, TempCo="200 ppm/C", Tolerance_%=1, Value1=1%, Value2=0.1W, Value_Code=1R00, ValueDisplayed=1.00
R808 R810: "RES, 0, 5%, 0.063 W, 0402", Manufacturer=Vishay-Dale, Power_W=0.063, Supplier Part Number 1=541-0.0JCT-ND, TempCo="200 ppm/C", Tolerance_%=5, Value1=5%, Value2=0.063W, Value_Code=0000, ValueDisplayed=0
R809 R814: "RES, 10.0 k, 1%, 0.1 W, 0603", Manufacturer=Vishay-Dale, Power_W=0.1, Supplier Part Number 1=541-10.0KHCT-ND, TempCo="100 ppm/C", Tolerance_%=1, Value1=1%, Value2=0.1W, Value_Code=10k0, ValueDisplayed=10.0k
R812: "RES, 3.09 k, 1%, 0.063 W, 0402", Manufacturer=Vishay-Dale, Power_W=0.063, Supplier Part Number 1=541-3.09KLCT-ND, TempCo="100 ppm/C", Tolerance_%=1, Value1=1%, Value2=0.063W, Value_Code=3k09, ValueDisplayed=3.09k
R815 R816: "RES, 5.1 k, 5%, 0.063 W, 0402", Manufacturer=Vishay-Dale, Power_W=0.063, Supplier Part Number 1=541-5.1KJCT-ND, TempCo="200 ppm/C", Tolerance_%=5, Value1=5%, Value2=0.063W, Value_Code=5k10, ValueDisplayed=5.1k
TP800 TP801 TP802 TP803: library part CMP-0055001-1, "PCB Pin, Swage Mount, TH", Manufacturer=Mill-Max, Supplier Part Number 1=3104-200340000080-ND
U800 U801: "Automotive Catalog Adjustable Precision Shunt Regulator, 34 ppm / degC, 100 mA, -40 to 125 degC, 3-pin SOT-23 (DBZ), Green (RoHS & no Sb/Br)", Alternate Manufacturer="Texas Instruments", Alternate PartNumber=Equivalent, Rating=Automotive, Supplier Part Number 1=296-21853-2-ND, Temp Coeff(Typ)(ppm/ degree C)=34
U802: library part CMP-0083997-1, "4-A, 6-A, 5.7-kVRMS Isolated Dual-Channel Gate Driver with Enable, DWK0014A (SOIC-14)", Alternate Manufacturer="Texas Instruments", Alternate PartNumber=UCC21530QDWKQ1

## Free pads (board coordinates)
  round 2.54 hole 2.032: 1(2.54,27.94) 1(2.54,33.02) 1(5.08,25.4) 1(5.093,30.48) 1(12.663,33.02) 1(15.247,30.48) 1(19.05,30.48) 1(21.59,33.02)
  oval 2.286x2.794 hole 1.702: 1(2.794,6.35) 1(5.334,6.35) 1(7.874,6.35) 1(12.954,6.35) 1(21.082,6.35) 1(23.622,6.35) 1(26.162,6.35) 1(31.242,6.35)
  round 0.56 hole 0.86 unplated mask+0.102: 1(35.83,19.098) 1(35.83,21.098) 1(35.83,23.098) 1(35.83,25.098) 1(37.83,19.098) 1(37.83,21.098) 1(37.83,23.098) 1(37.83,25.098)

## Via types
v1: diameter 0.508, hole 0.254, Top Layer to Bottom Layer, 33 vias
